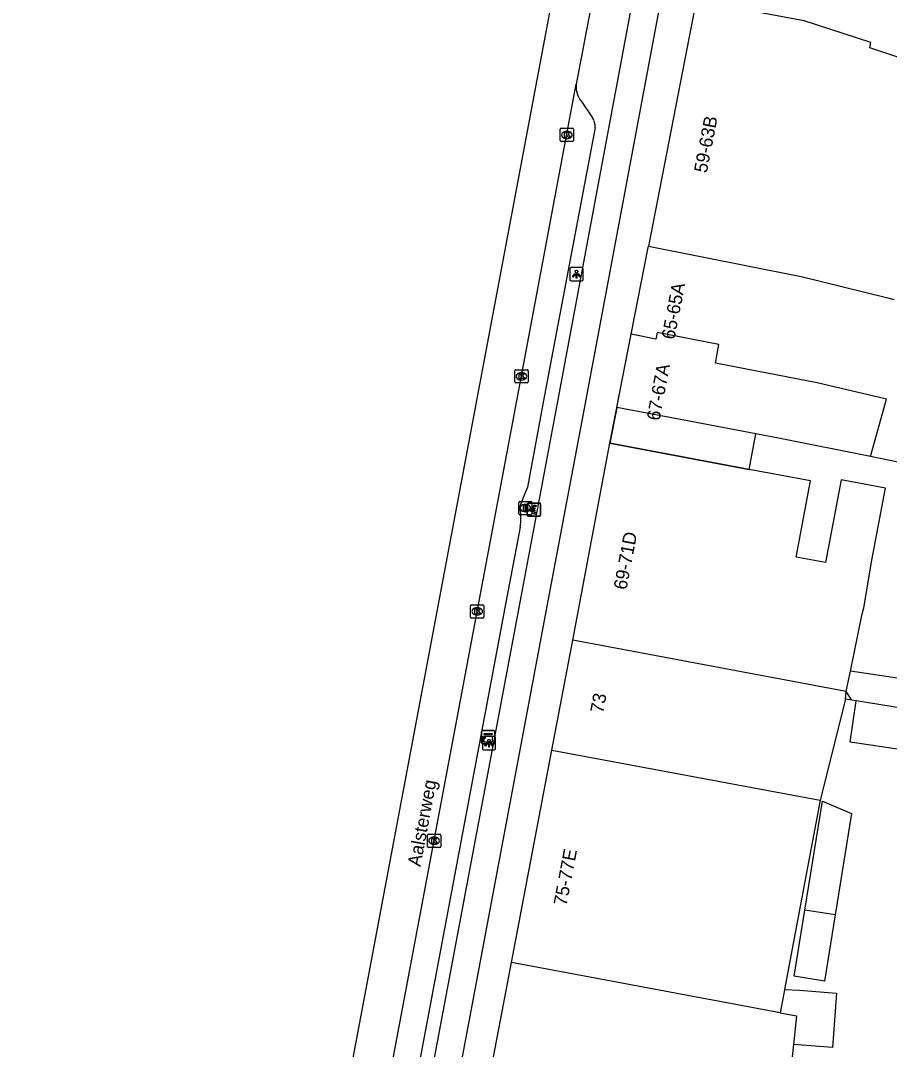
# Model space of a CAD drawing. Extents: x 161845 to 162341, y 381620 to 382158.
# Drawn here: x 161857.3 to 161922.8, y 381850 to 381927.5 of the extents above; entities that cross this region are included whole.
import ezdxf

# ---------------------------------------------------------------- set-up
doc = ezdxf.new("R2010")
doc.units = 0
for name, color, linetype in [('IMGEO_Betaalautomaat', 7, 'Continuous'), ('IMGEO_Brandkraan', 7, 'Continuous'), ('IMGEO_Erf', 7, 'Continuous'), ('IMGEO_Fietspad_gesloten', 7, 'Continuous'), ('IMGEO_Kast', 7, 'Continuous'), ('IMGEO_Kolk', 7, 'Continuous'), ('IMGEO_Lichtpunt', 7, 'Continuous'), ('IMGEO_Openbare_ruimte_label', 7, 'Continuous'), ('IMGEO_OVBaan_gesloten', 7, 'Continuous'), ('IMGEO_Pand', 7, 'Continuous'), ('IMGEO_Pand_nummerreeks', 7, 'Continuous'), ('IMGEO_Pand_overbouw', 7, 'Continuous'), ('IMGEO_Parkeervlak_open', 7, 'Continuous'), ('IMGEO_Rijbaan_lokaal_gesloten', 7, 'Continuous'), ('IMGEO_Voetpad_open', 7, 'Continuous')]:
    doc.layers.add(name, color=color, linetype=linetype)

msp = doc.modelspace()

# ---------------------------------------------------------------- linework, layer by layer
at = {"layer": 'IMGEO_Betaalautomaat'}
for p, q in [((161895.586, 381891.176), (161896.427, 381891.176)), ((161896.427, 381891.176), (161895.586, 381891.176)), ((161895.511, 381890.252), (161895.511, 381891.093)), ((161895.511, 381891.093), (161895.511, 381890.252)), ((161895.794, 381890.64), (161895.794, 381890.708)), ((161895.915, 381890.708), (161895.915, 381890.64)), ((161896.173, 381890.981), (161896.156, 381890.881)), ((161896.16, 381890.475), (161896.182, 381890.388)), ((161896.51, 381891.102), (161896.51, 381890.261)), ((161896.51, 381890.261), (161896.51, 381891.102)), ((161896.436, 381890.177), (161895.595, 381890.177)), ((161895.595, 381890.177), (161896.436, 381890.177))]:
    msp.add_line(p, q, dxfattribs=at)
for points in [[(161895.794, 381890.708), (161895.725, 381890.708), (161895.725, 381890.777), (161895.804, 381890.777)], [(161895.799, 381890.571), (161895.725, 381890.571), (161895.725, 381890.64), (161895.794, 381890.64)], [(161895.926, 381890.777), (161896.073, 381890.777), (161896.073, 381890.708), (161895.915, 381890.708)], [(161895.915, 381890.64), (161896.073, 381890.64), (161896.073, 381890.571), (161895.929, 381890.571)]]:
    msp.add_lwpolyline(points, dxfattribs=at)
for centre, radius, start, end in [((161895.589, 381891.099), 0.0779, 92.4484, 184.28452), ((161895.589, 381891.099), 0.0779, 92.4484, 184.28452), ((161896.433, 381891.099), 0.0779, 2.4484, 94.28452), ((161896.433, 381891.099), 0.0779, 2.4484, 94.28452), ((161896.06, 381890.626), 0.267, 191.80956, 297.03891), ((161896.087, 381890.701), 0.293, 73.01398, 165.01395), ((161896.093, 381890.714), 0.179, 69.32359, 159.56827), ((161896.093, 381890.641), 0.179, 202.76249, 291.86925), ((161895.589, 381890.255), 0.0779, 182.4484, 274.28452), ((161895.589, 381890.255), 0.0779, 182.4484, 274.28452), ((161896.433, 381890.255), 0.0779, 272.4484, 4.28452), ((161896.433, 381890.255), 0.0779, 272.4484, 4.28452)]:
    msp.add_arc(centre, radius, start, end, dxfattribs=at)
at = {"layer": 'IMGEO_Brandkraan'}
for p, q in [((161894.864, 381890.368), (161894.864, 381891.22)), ((161894.939, 381891.294), (161895.791, 381891.294)), ((161895.865, 381891.22), (161895.865, 381890.368)), ((161895.375, 381890.514), (161895.35, 381890.514)), ((161895.352, 381891.074), (161895.377, 381891.074)), ((161895.791, 381890.294), (161894.939, 381890.294))]:
    msp.add_line(p, q, dxfattribs=at)
for points in [[(161894.864, 381890.368), (161894.864, 381891.22)], [(161894.939, 381891.294), (161895.791, 381891.294)], [(161895.865, 381891.22), (161895.865, 381890.368)], [(161895.212, 381890.994), (161895.212, 381890.594), (161895.425, 381890.594)], [(161895.443, 381890.994), (161895.212, 381890.994)], [(161895.391, 381890.913), (161895.337, 381890.913), (161895.337, 381890.837)], [(161895.337, 381890.837), (161895.39, 381890.837)], [(161895.399, 381890.761), (161895.337, 381890.761), (161895.337, 381890.68)], [(161895.337, 381890.68), (161895.399, 381890.68)], [(161895.791, 381890.294), (161894.939, 381890.294)]]:
    msp.add_lwpolyline(points, dxfattribs=at)
for centre, radius, start, end in [((161894.941, 381891.218), 0.0765, 91.55205, 178.44795), ((161894.941, 381891.218), 0.0765, 91.55205, 178.44795), ((161895.789, 381891.218), 0.0765, 1.55205, 88.44795), ((161895.789, 381891.218), 0.0765, 1.55205, 88.44795), ((161894.941, 381890.37), 0.0765, 181.55205, 268.44795), ((161894.941, 381890.37), 0.0765, 181.55205, 268.44795), ((161895.392, 381890.875), 0.0379, 267.82845, 90.93552), ((161895.4, 381890.72), 0.0404, 269.87594, 90.50774), ((161895.431, 381890.845), 0.251, 268.66757, 293.53466), ((161895.447, 381890.849), 0.145, 59.4692, 91.53667), ((161895.472, 381890.896), 0.0922, 285.51372, 58.15012), ((161895.477, 381890.704), 0.105, 301.31148, 78.98903), ((161895.789, 381890.37), 0.0765, 271.55205, 358.44795), ((161895.789, 381890.37), 0.0765, 271.55205, 358.44795)]:
    msp.add_arc(centre, radius, start, end, dxfattribs=at)
for centre, major_axis, ratio, start_param, end_param in [((161895.351, 381890.794), (-0.387, 0.002), 0.722429, 4.712389, 7.853982), ((161895.376, 381890.794), (-0.39, 0.002), 0.717154, 1.570796, 4.712389)]:
    msp.add_ellipse(centre, major_axis=major_axis, ratio=ratio, start_param=start_param, end_param=end_param, dxfattribs=at)
at = {"layer": 'IMGEO_Erf'}
msp.add_lwpolyline([(161919.974, 381876.316), (161919.486, 381876.396)], dxfattribs=at)
at = {"layer": 'IMGEO_Fietspad_gesloten'}
for points in [[(161857.316, 381682.246), (161862.987, 381712.892), (161864.774, 381722.548), (161869.854, 381750), (161870.207, 381751.91), (161895.081, 381884.229), (161897.858, 381899.101), (161916.698, 382000), (161921.558, 382026.031), (161926.346, 382051.921)], [(161907.39, 381938.834), (161899.866, 381898.705), (161897.095, 381883.929), (161872.236, 381751.615), (161871.936, 381750), (161866.402, 381720.165)]]:
    msp.add_lwpolyline(points, dxfattribs=at)
at = {"layer": 'IMGEO_Kast'}
for p, q in [((161892.065, 381873.089), (161892.065, 381873.93)), ((161892.065, 381873.93), (161892.065, 381873.089)), ((161892.14, 381874.014), (161892.981, 381874.014)), ((161892.981, 381874.014), (161892.14, 381874.014)), ((161893.065, 381873.939), (161893.065, 381873.098)), ((161893.065, 381873.098), (161893.065, 381873.939)), ((161892.99, 381873.014), (161892.149, 381873.014)), ((161892.149, 381873.014), (161892.99, 381873.014))]:
    msp.add_line(p, q, dxfattribs=at)
for points in [[(161892.26, 381873.804), (161892.86, 381873.804), (161892.86, 381873.719), (161892.26, 381873.719), (161892.26, 381873.804)], [(161892.26, 381873.629), (161892.86, 381873.629), (161892.86, 381873.14), (161892.26, 381873.14), (161892.26, 381873.629)]]:
    msp.add_lwpolyline(points, dxfattribs=at)
msp.add_circle((161892.344, 381873.478), 0.0377, dxfattribs=at)
for centre, start, end in [((161892.143, 381873.936), 92.4484, 184.28452), ((161892.143, 381873.936), 92.4484, 184.28452), ((161892.987, 381873.936), 2.4484, 94.28452), ((161892.987, 381873.936), 2.4484, 94.28452), ((161892.143, 381873.092), 182.4484, 274.28452), ((161892.143, 381873.092), 182.4484, 274.28452), ((161892.987, 381873.092), 272.4484, 4.28452), ((161892.987, 381873.092), 272.4484, 4.28452)]:
    msp.add_arc(centre, 0.0779, start, end, dxfattribs=at)
at = {"layer": 'IMGEO_Kolk'}
for p, q in [((161897.999, 381918.495), (161897.999, 381919.347)), ((161898.074, 381919.421), (161898.926, 381919.421)), ((161898.487, 381919.201), (161898.512, 381919.201)), ((161899, 381919.347), (161899, 381918.495)), ((161898.926, 381918.421), (161898.074, 381918.421)), ((161898.51, 381918.641), (161898.485, 381918.641)), ((161894.644, 381901.226), (161895.496, 381901.226)), ((161894.569, 381900.3), (161894.569, 381901.152)), ((161895.08, 381900.446), (161895.055, 381900.446)), ((161895.057, 381901.006), (161895.082, 381901.006)), ((161895.57, 381901.152), (161895.57, 381900.3)), ((161895.496, 381900.226), (161894.644, 381900.226)), ((161891.235, 381882.579), (161891.235, 381883.431)), ((161891.31, 381883.505), (161892.162, 381883.505)), ((161892.236, 381883.431), (161892.236, 381882.579)), ((161891.746, 381882.725), (161891.721, 381882.725)), ((161891.723, 381883.285), (161891.748, 381883.285)), ((161892.162, 381882.505), (161891.31, 381882.505)), ((161887.987, 381865.292), (161887.987, 381866.144)), ((161888.062, 381866.218), (161888.914, 381866.218)), ((161888.475, 381865.998), (161888.5, 381865.998)), ((161888.988, 381866.144), (161888.988, 381865.292)), ((161888.914, 381865.218), (161888.062, 381865.218)), ((161888.498, 381865.438), (161888.473, 381865.438))]:
    msp.add_line(p, q, dxfattribs=at)
for points in [[(161897.999, 381918.495), (161897.999, 381919.347)], [(161898.074, 381919.421), (161898.926, 381919.421)], [(161898.32, 381919.121), (161898.443, 381919.121), (161898.443, 381918.97), (161898.573, 381919.121), (161898.737, 381919.121), (161898.591, 381918.97), (161898.744, 381918.721), (161898.592, 381918.721), (161898.507, 381918.885), (161898.443, 381918.818), (161898.443, 381918.721), (161898.32, 381918.721), (161898.32, 381919.121)], [(161899, 381919.347), (161899, 381918.495)], [(161898.926, 381918.421), (161898.074, 381918.421)], [(161894.644, 381901.226), (161895.496, 381901.226)], [(161894.569, 381900.3), (161894.569, 381901.152)], [(161894.89, 381900.926), (161895.013, 381900.926), (161895.013, 381900.775), (161895.143, 381900.926), (161895.307, 381900.926), (161895.161, 381900.775), (161895.314, 381900.526), (161895.162, 381900.526), (161895.077, 381900.69), (161895.013, 381900.623), (161895.013, 381900.526), (161894.89, 381900.526), (161894.89, 381900.926)], [(161895.57, 381901.152), (161895.57, 381900.3)], [(161895.496, 381900.226), (161894.644, 381900.226)], [(161891.235, 381882.579), (161891.235, 381883.431)], [(161891.31, 381883.505), (161892.162, 381883.505)], [(161892.236, 381883.431), (161892.236, 381882.579)], [(161891.556, 381883.205), (161891.679, 381883.205), (161891.679, 381883.054), (161891.809, 381883.205), (161891.973, 381883.205), (161891.827, 381883.054), (161891.98, 381882.805), (161891.828, 381882.805), (161891.743, 381882.969), (161891.679, 381882.902), (161891.679, 381882.805), (161891.556, 381882.805), (161891.556, 381883.205)], [(161892.162, 381882.505), (161891.31, 381882.505)], [(161887.987, 381865.292), (161887.987, 381866.144)], [(161888.062, 381866.218), (161888.914, 381866.218)], [(161888.308, 381865.918), (161888.431, 381865.918), (161888.431, 381865.767), (161888.561, 381865.918), (161888.725, 381865.918), (161888.579, 381865.767), (161888.732, 381865.518), (161888.58, 381865.518), (161888.495, 381865.682), (161888.431, 381865.615), (161888.431, 381865.518), (161888.308, 381865.518), (161888.308, 381865.918)], [(161888.988, 381866.144), (161888.988, 381865.292)], [(161888.914, 381865.218), (161888.062, 381865.218)]]:
    msp.add_lwpolyline(points, dxfattribs=at)
for centre, start, end in [((161898.076, 381919.345), 91.55205, 178.44795), ((161898.076, 381919.345), 91.55205, 178.44795), ((161898.924, 381919.345), 1.55205, 88.44795), ((161898.924, 381919.345), 1.55205, 88.44795), ((161898.076, 381918.497), 181.55205, 268.44795), ((161898.076, 381918.497), 181.55205, 268.44795), ((161898.924, 381918.497), 271.55205, 358.44795), ((161898.924, 381918.497), 271.55205, 358.44795), ((161894.646, 381901.15), 91.55205, 178.44795), ((161894.646, 381901.15), 91.55205, 178.44795), ((161895.494, 381901.15), 1.55205, 88.44795), ((161895.494, 381901.15), 1.55205, 88.44795), ((161894.646, 381900.302), 181.55205, 268.44795), ((161894.646, 381900.302), 181.55205, 268.44795), ((161895.494, 381900.302), 271.55205, 358.44795), ((161895.494, 381900.302), 271.55205, 358.44795), ((161891.312, 381883.429), 91.55205, 178.44795), ((161891.312, 381883.429), 91.55205, 178.44795), ((161892.16, 381883.429), 1.55205, 88.44795), ((161892.16, 381883.429), 1.55205, 88.44795), ((161891.312, 381882.581), 181.55205, 268.44795), ((161891.312, 381882.581), 181.55205, 268.44795), ((161892.16, 381882.581), 271.55205, 358.44795), ((161892.16, 381882.581), 271.55205, 358.44795), ((161888.064, 381866.142), 91.55205, 178.44795), ((161888.064, 381866.142), 91.55205, 178.44795), ((161888.912, 381866.142), 1.55205, 88.44795), ((161888.912, 381866.142), 1.55205, 88.44795), ((161888.064, 381865.294), 181.55205, 268.44795), ((161888.064, 381865.294), 181.55205, 268.44795), ((161888.912, 381865.294), 271.55205, 358.44795), ((161888.912, 381865.294), 271.55205, 358.44795)]:
    msp.add_arc(centre, 0.0765, start, end, dxfattribs=at)
for centre, major_axis, ratio, start_param, end_param in [((161898.486, 381918.921), (-0.387, 0.002), 0.722429, 4.712389, 7.853982), ((161898.511, 381918.921), (-0.39, 0.002), 0.717154, 1.570796, 4.712389), ((161895.056, 381900.726), (-0.387, 0.002), 0.722429, 4.712389, 7.853982), ((161895.081, 381900.726), (-0.39, 0.002), 0.717154, 1.570796, 4.712389), ((161891.722, 381883.005), (-0.387, 0.002), 0.722429, 4.712389, 7.853982), ((161891.747, 381883.005), (-0.39, 0.002), 0.717154, 1.570796, 4.712389), ((161888.474, 381865.718), (-0.387, 0.002), 0.722429, 4.712389, 7.853982), ((161888.499, 381865.718), (-0.39, 0.002), 0.717154, 1.570796, 4.712389)]:
    msp.add_ellipse(centre, major_axis=major_axis, ratio=ratio, start_param=start_param, end_param=end_param, dxfattribs=at)
at = {"layer": 'IMGEO_Lichtpunt'}
for p, q in [((161898.722, 381908.824), (161898.722, 381908.017)), ((161898.722, 381908.824), (161898.722, 381908.017)), ((161899.624, 381908.919), (161898.816, 381908.919)), ((161899.624, 381908.919), (161898.816, 381908.919)), ((161899.718, 381908.017), (161899.718, 381908.824)), ((161899.718, 381908.017), (161899.718, 381908.824)), ((161898.816, 381907.923), (161899.624, 381907.923)), ((161898.816, 381907.923), (161899.624, 381907.923)), ((161892.127, 381873.472), (161892.127, 381872.665)), ((161892.127, 381873.472), (161892.127, 381872.665)), ((161893.029, 381873.567), (161892.221, 381873.567)), ((161893.029, 381873.567), (161892.221, 381873.567)), ((161893.123, 381872.665), (161893.123, 381873.472)), ((161893.123, 381872.665), (161893.123, 381873.472)), ((161892.221, 381872.571), (161893.029, 381872.571)), ((161892.221, 381872.571), (161893.029, 381872.571))]:
    msp.add_line(p, q, dxfattribs=at)
for points in [[(161899.096, 381908.488), (161899.135, 381908.46), (161898.947, 381908.198), (161898.909, 381908.225), (161899.096, 381908.488)], [(161899.198, 381908.44), (161899.245, 381908.44), (161899.245, 381908.118), (161899.198, 381908.118), (161899.198, 381908.44)], [(161899.308, 381908.46), (161899.346, 381908.487), (161899.533, 381908.225), (161899.494, 381908.197), (161899.308, 381908.46)], [(161892.501, 381873.136), (161892.54, 381873.108), (161892.352, 381872.846), (161892.314, 381872.873), (161892.501, 381873.136)], [(161892.603, 381873.088), (161892.65, 381873.088), (161892.65, 381872.766), (161892.603, 381872.766), (161892.603, 381873.088)], [(161892.713, 381873.108), (161892.751, 381873.135), (161892.938, 381872.873), (161892.899, 381872.845), (161892.713, 381873.108)]]:
    msp.add_lwpolyline(points, dxfattribs=at)
for centre in [(161899.221, 381908.622), (161892.626, 381873.27)]:
    msp.add_circle(centre, 0.0994, dxfattribs=at)
for centre, start, end in [((161898.816, 381908.824), 90, 180), ((161898.816, 381908.824), 90, 180), ((161899.624, 381908.824), 0, 90), ((161899.624, 381908.824), 0, 90), ((161898.816, 381908.017), 180, 270), ((161898.816, 381908.017), 180, 270), ((161899.624, 381908.017), 270, 0), ((161899.624, 381908.017), 270, 360), ((161892.221, 381873.472), 90, 180), ((161892.221, 381873.472), 90, 180), ((161893.029, 381873.472), 0, 90), ((161893.029, 381873.472), 0, 90), ((161892.221, 381872.665), 180, 270), ((161892.221, 381872.665), 180, 270), ((161893.029, 381872.665), 270, 0), ((161893.029, 381872.665), 270, 360)]:
    msp.add_arc(centre, 0.0946, start, end, dxfattribs=at)
at = {"layer": 'IMGEO_OVBaan_gesloten'}
msp.add_lwpolyline([(161858.651, 381720.96), (161859.425, 381726.158), (161861.132, 381736.231), (161869.606, 381781.344), (161897.211, 381928.16), (161915.531, 382025.949), (161915.767, 382027.092)], dxfattribs=at)
at = {"layer": 'IMGEO_Pand'}
for points in [[(161908.231, 381929.021), (161904.636, 381910.55)], [(161926.864, 381923.63), (161925.907, 381923.95), (161921.324, 381925.485), (161921.399, 381925.893), (161916.384, 381927.527), (161908.231, 381929.021)], [(161903.341, 381903.897), (161904.615, 381910.446), (161904.636, 381910.55)], [(161904.636, 381910.55), (161916.152, 381908.245), (161922.591, 381906.67), (161923.069, 381906.553), (161923.168, 381906.529)], [(161902.268, 381898.386), (161903.341, 381903.897)], [(161921.374, 381894.671), (161922.583, 381899.012), (161917.356, 381900.23), (161909.687, 381901.727), (161909.961, 381903.128), (161905.299, 381904.038), (161905.201, 381903.534), (161903.341, 381903.897)], [(161921.374, 381894.671), (161914.564, 381896.043), (161912.75, 381896.389), (161907.18, 381897.45), (161902.268, 381898.386)], [(161924.39, 381897.931), (161923.437, 381894.255), (161921.374, 381894.671)], [(161898.938, 381880.835), (161901.744, 381895.676)], [(161919.869, 381878.497), (161920.712, 381882.567), (161920.836, 381883.1), (161920.879, 381883.283), (161921.485, 381886.86), (161922.502, 381892.298), (161919.164, 381892.922), (161917.997, 381886.682), (161915.788, 381887.095), (161916.864, 381892.849), (161912.24, 381893.714), (161906.659, 381894.757), (161901.744, 381895.676)], [(161929.808, 381881.571), (161929.749, 381881.177), (161929.642, 381880.46), (161929.229, 381877.704), (161924.153, 381878.464), (161924.063, 381877.869), (161919.869, 381878.497)], [(161897.372, 381872.555), (161898.938, 381880.835)], [(161919.552, 381876.967), (161898.938, 381880.835)], [(161919.552, 381876.967), (161919.603, 381877.215), (161919.869, 381878.497)], [(161919.486, 381876.396), (161919.552, 381876.967)], [(161919.974, 381876.316), (161919.552, 381876.967)], [(161919.486, 381876.396), (161917.589, 381868.765)], [(161923.414, 381872.627), (161919.842, 381873.159), (161920.308, 381876.262)], [(161920.308, 381876.262), (161919.974, 381876.316)], [(161923.872, 381875.678), (161920.308, 381876.262)], [(161894.318, 381856.539), (161897.372, 381872.555)], [(161897.372, 381872.555), (161917.589, 381868.765)], [(161917.589, 381868.765), (161914.902, 381854.491)], [(161916.435, 381860.485), (161917.755, 381868.694), (161919.938, 381867.762), (161918.709, 381860.12)], [(161918.709, 381860.12), (161917.918, 381855.141), (161915.635, 381855.508), (161916.435, 381860.485)], [(161918.709, 381860.12), (161916.435, 381860.485)], [(161891.353, 381840.988), (161894.318, 381856.539)], [(161914.574, 381852.746), (161894.318, 381856.539)], [(161914.902, 381854.491), (161914.848, 381854.2), (161914.574, 381852.746)], [(161914.902, 381854.491), (161916.022, 381854.453), (161918.826, 381854.233), (161918.51, 381850.131), (161915.575, 381850.361)], [(161914.574, 381852.746), (161915.81, 381852.515), (161915.575, 381850.361)], [(161915.575, 381850.361), (161914.718, 381842.499)]]:
    msp.add_lwpolyline(points, dxfattribs=at)
at = {"layer": 'IMGEO_Pand_overbouw'}
msp.add_lwpolyline([(161912.75, 381896.389), (161907.18, 381897.45), (161902.268, 381898.386), (161902.239, 381898.237), (161901.744, 381895.676), (161906.659, 381894.757), (161912.24, 381893.714)], close=True, dxfattribs=at)
at = {"layer": 'IMGEO_Parkeervlak_open'}
for points in [[(161899.588, 381921.451), (161900.429, 381920.223)], [(161900.616, 381919.482), (161896.821, 381899.305), (161895.517, 381892.371), (161895.218, 381891.646), (161894.941, 381890.914)], [(161894.979, 381889.343), (161893.959, 381884.074), (161881.221, 381816.302), (161880.899, 381815.584)]]:
    msp.add_lwpolyline(points, dxfattribs=at)
for centre, radius, start, end in [((161900.859, 381922.534), 1.67, 172.85869, 220.4339), ((161899.475, 381919.588), 1.146, 354.67877, 33.64828), ((161890.246, 381890.014), 4.78, 351.925, 10.84625)]:
    msp.add_arc(centre, radius, start, end, dxfattribs=at)
at = {"layer": 'IMGEO_Rijbaan_lokaal_gesloten'}
for points in [[(161905.11, 381954.479), (161905.076, 381954.299), (161904.686, 381952.125), (161903.787, 381947.27), (161902.001, 381937.624), (161901.082, 381932.662), (161899.202, 381922.742)], [(161871.456, 381775.156), (161894.868, 381899.69), (161899.202, 381922.742)]]:
    msp.add_lwpolyline(points, dxfattribs=at)
at = {"layer": 'IMGEO_Voetpad_open'}
msp.add_lwpolyline([(161901.744, 381895.676), (161902.239, 381898.237), (161902.268, 381898.386)], dxfattribs=at)

# ---------------------------------------------------------------- texts
at = {"layer": 'IMGEO_Openbare_ruimte_label'}
msp.add_text('Aalsterweg', height=1, rotation=79.45427, dxfattribs=at).set_placement((161887.461, 381863.717))
at = {"layer": 'IMGEO_Pand_nummerreeks'}
for s, rotation, p in [('59-63B', 78.98796, (161909.041, 381916.011)), ('65-65A', 78.98796, (161906.596, 381903.448)), ('67-67A', 79.45206, (161905.482, 381897.334)), ('69-71D', 79.29163, (161902.986, 381884.585)), ('73', 79.29013, (161901.224, 381875.274)), ('75-77E', 79.20569, (161898.463, 381860.761))]:
    msp.add_text(s, height=1, rotation=rotation, dxfattribs=at).set_placement(p)

doc.saveas('drawing.dxf')
